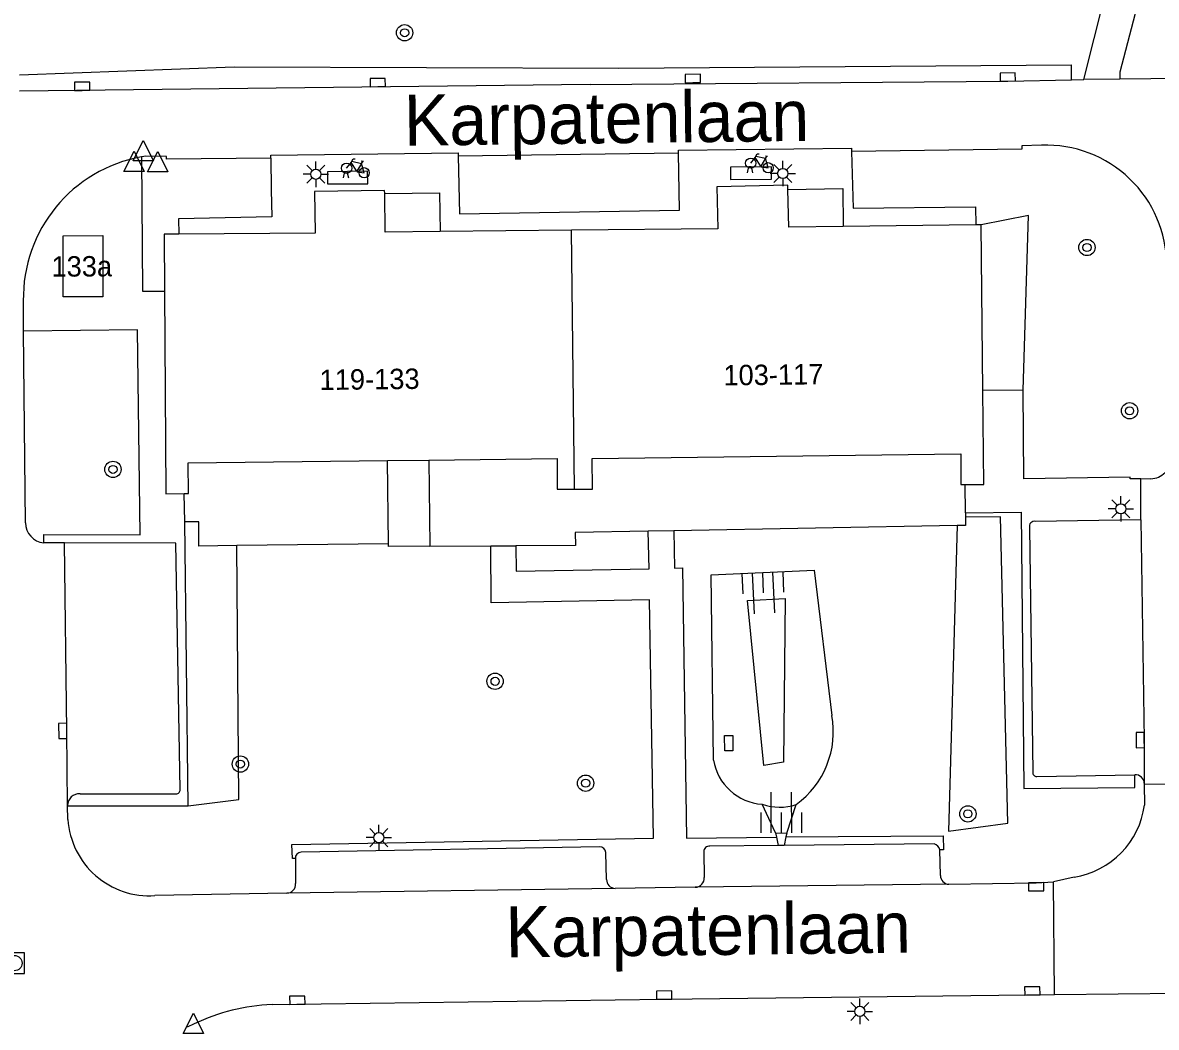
# Model space of a CAD drawing. Extents: x 132994 to 136000, y 393499 to 395512.
# Drawn here: x 133882.7 to 133938.3, y 394606.9 to 394656.2 of the extents above; entities that cross this region are included whole.
import ezdxf

# ---------------------------------------------------------------- set-up
doc = ezdxf.new("R2010")
doc.units = 0
for name, color, linetype in [('gg-afsc-erfafscheiding', 7, 'Continuous'), ('gg-anno-huisnummerreeks BGT', 7, 'Continuous'), ('gg-anno-openbare ruimte label', 7, 'Continuous'), ('gg-bbg-bijgebouw', 7, 'Continuous'), ('gg-bbg-hoofdgebouw', 7, 'Continuous'), ('gg-bbg-luifel en loopbrug', 7, 'Continuous'), ('gg-bbg-tussenscheiding', 7, 'Continuous'), ('gg-knt-bovenkant onderkant talud', 7, 'Continuous'), ('gg-knt-verharding', 7, 'Continuous'), ('gg-knt-verharding nz', 7, 'Continuous'), ('gt-grn-groengrens', 7, 'Continuous'), ('gt-symb-boom', 7, 'Continuous'), ('gt-symb-fietsenrek', 7, 'Continuous'), ('gt-symb-kolk', 7, 'Continuous'), ('gt-symb-kolk center center', 7, 'Continuous'), ('gt-symb-lichtmast', 7, 'Continuous'), ('gt-symb-rioolschacht', 7, 'Continuous'), ('gt-symb-talud symbool', 7, 'Continuous'), ('gt-symb-waterafsluiter', 7, 'Continuous')]:
    doc.layers.add(name, color=color, linetype=linetype)

# ---------------------------------------------------------------- blocks, each defined once
blk = doc.blocks.new('gt0-KOLK')
at = {"layer": 'gt-symb-kolk'}
blk.add_lwpolyline([(0, 0), (0.375, 0), (0.375, 0.4), (-0.375, 0.4), (-0.375, 0), (0, 0)], dxfattribs=at)
blk = doc.blocks.new('gt0-BOOM')
at = {"layer": 'gt-symb-boom'}
for radius in [0.4, 0.2]:
    blk.add_circle((0, 0), radius, dxfattribs=at)
blk = doc.blocks.new('gt0-LMAST')
at = {"layer": 'gt-symb-lichtmast'}
for p, q in [((-0.005, 0.246), (-0.005, 0.621)), ((-0.182, 0.173), (-0.447, 0.438)), ((0.172, 0.173), (0.437, 0.438)), ((-0.255, -0.004), (-0.63, -0.004)), ((-0.182, -0.181), (-0.447, -0.446)), ((-0.005, -0.254), (-0.005, -0.629)), ((0.437, -0.446), (0.172, -0.181)), ((0.245, -0.004), (0.62, -0.004))]:
    blk.add_line(p, q, dxfattribs=at)
blk.add_circle((-0.005, -0.004), 0.25, dxfattribs=at)
blk = doc.blocks.new('gt0-KOLKCC')
at = {"layer": 'gt-symb-kolk center center'}
blk.add_lwpolyline([(-0.375, 0.2), (0.375, 0.2), (0.375, -0.2), (-0.375, -0.2)], close=True, dxfattribs=at)
blk = doc.blocks.new('gt0-TALUD_1')
at = {"layer": 'gt-symb-talud symbool'}
for p, q in [((-1, -1), (-1, 0)), ((-0.5, -2), (-0.5, 0)), ((0, -1), (0, 0)), ((0.5, -2), (0.5, 0)), ((1, -1), (1, 0))]:
    blk.add_line(p, q, dxfattribs=at)
blk = doc.blocks.new('gt0-FREK')
at = {"layer": 'gt-symb-fietsenrek'}
for p, q in [((0.259, 0.762), (0.294, 0.823)), ((0.54, 0.335), (0.259, 0.762)), ((0.294, 0.823), (0.767, 0.714)), ((0.767, 0.714), (0.54, 0.335)), ((0.757, 0.841), (0.866, 0.816)), ((0.767, 0.714), (0.84, 0.822)), ((0.895, 0.252), (0.767, 0.714))]:
    blk.add_line(p, q, dxfattribs=at)
for points in [[(0.036, 0.476), (0.228, 0.708), (0.259, 0.762)], [(0.294, 0.823), (0.36, 0.937), (0.452, 0.935)], [(-0.124, 0), (-0.047, 0.312), (0.053, 0.312), (0.12, 0)], [(0.54, 0.335), (0.555, 0.305), (0.895, 0.252)]]:
    blk.add_lwpolyline(points, dxfattribs=at)
for centre in [(0.036, 0.476), (0.895, 0.252)]:
    blk.add_circle(centre, 0.252, dxfattribs=at)
blk = doc.blocks.new('gt0-WAFSL')
at = {"layer": 'gt-symb-waterafsluiter'}
for p, q in [((-0.5, -0.333), (0, 0.667)), ((0, 0.667), (0.5, -0.333)), ((0.5, -0.333), (-0.5, -0.333))]:
    blk.add_line(p, q, dxfattribs=at)
blk = doc.blocks.new('gt0-RS')
at = {"layer": 'gt-symb-rioolschacht'}
blk.add_lwpolyline([(-0.5, -0.5), (0.5, -0.5), (0.5, 0.5), (-0.5, 0.5)], close=True, dxfattribs=at)
blk.add_circle((0, 0), 0.375, dxfattribs=at)

msp = doc.modelspace()

# ---------------------------------------------------------------- linework, layer by layer
at = {"layer": 'gg-afsc-erfafscheiding'}
for p, q in [((133928.9, 394632.136), (133928.888, 394633.522)), ((133928.9, 394632.136), (133928.902, 394631.927)), ((133928.5, 394631.51), (133914.598, 394631.256)), ((133914.598, 394631.256), (133913.345, 394631.233)), ((133900.597, 394630.606), (133893.156, 394630.526)), ((133902.632, 394630.494), (133905.612, 394630.512)), ((133905.612, 394630.512), (133906.851, 394630.52))]:
    msp.add_line(p, q, dxfattribs=at)
for points in [[(133928.902, 394631.927), (133928.905, 394631.517), (133928.5, 394631.51)], [(133893.156, 394630.526), (133891.301, 394630.506), (133891.287, 394631.695), (133890.599, 394631.687)], [(133913.345, 394631.233), (133909.755, 394631.167), (133909.767, 394630.538), (133906.851, 394630.52)]]:
    msp.add_lwpolyline(points, dxfattribs=at)
at = {"layer": 'gg-bbg-bijgebouw'}
for p, q in [((133900.597, 394630.606), (133900.549, 394634.693)), ((133902.583, 394634.717), (133902.632, 394630.494))]:
    msp.add_line(p, q, dxfattribs=at)
msp.add_lwpolyline([(133902.632, 394630.494), (133900.598, 394630.487), (133900.597, 394630.606)], dxfattribs=at)
at = {"layer": 'gg-bbg-hoofdgebouw'}
for p, q in [((133890.308, 394645.805), (133889.59, 394645.8)), ((133889.59, 394645.8), (133889.61, 394643.007)), ((133909.569, 394645.995), (133903.128, 394645.928)), ((133929.411, 394646.257), (133922.91, 394646.181)), ((133929.67, 394646.26), (133929.411, 394646.257)), ((133929.753, 394638.129), (133929.67, 394646.26)), ((133889.61, 394643.007), (133889.68, 394633.121)), ((133929.8, 394633.53), (133929.753, 394638.129)), ((133900.549, 394634.693), (133902.583, 394634.717)), ((133928.68, 394633.52), (133928.888, 394633.522)), ((133928.888, 394633.522), (133929.8, 394633.53)), ((133890.574, 394633.076), (133890.79, 394633.08)), ((133908.88, 394633.29), (133909.727, 394633.295)), ((133909.727, 394633.295), (133910.6, 394633.3))]:
    msp.add_line(p, q, dxfattribs=at)
for points in [[(133920.194, 394647.99), (133920.19, 394648.2), (133916.71, 394648.12), (133916.75, 394646.07), (133909.569, 394645.995)], [(133922.91, 394646.181), (133920.23, 394646.15), (133920.194, 394647.99)], [(133900.412, 394647.789), (133900.41, 394647.95), (133896.97, 394647.9), (133897, 394645.85), (133890.308, 394645.805)], [(133903.128, 394645.928), (133900.44, 394645.9), (133900.412, 394647.789)], [(133886.59, 394642.72), (133884.64, 394642.72), (133884.63, 394645.72), (133886.58, 394645.73), (133886.59, 394642.72)], [(133890.79, 394633.08), (133890.77, 394634.58), (133900.549, 394634.693)], [(133902.583, 394634.717), (133908.87, 394634.79), (133908.88, 394633.29)], [(133910.6, 394633.3), (133910.59, 394634.8), (133928.67, 394635.02), (133928.68, 394633.52)], [(133889.68, 394633.121), (133889.68, 394633.06), (133890.574, 394633.076)]]:
    msp.add_lwpolyline(points, dxfattribs=at)
at = {"layer": 'gg-bbg-luifel en loopbrug'}
for points in [[(133920.194, 394647.99), (133922.889, 394648.042), (133922.91, 394646.181)], [(133900.412, 394647.789), (133903.108, 394647.828), (133903.128, 394645.928)]]:
    msp.add_lwpolyline(points, dxfattribs=at)
at = {"layer": 'gg-bbg-tussenscheiding'}
msp.add_line((133909.727, 394633.295), (133909.569, 394645.995), dxfattribs=at)
at = {"layer": 'gg-knt-bovenkant onderkant talud'}
for p, q in [((133919.588, 394616.443), (133918.931, 394617.845)), ((133920.134, 394616.426), (133920.601, 394617.829))]:
    msp.add_line(p, q, dxfattribs=at)
for points in [[(133916.542, 394620.007), (133916.429, 394629.086), (133921.481, 394629.317), (133922.351, 394622.191)], [(133919.982, 394619.903), (133919.011, 394619.737), (133918.205, 394627.831), (133920.06, 394627.937), (133919.982, 394619.903)]]:
    msp.add_lwpolyline(points, dxfattribs=at)
for centre, radius, start, end in [((133918.001, 394621.404), 4.421, 306.029, 10.2504), ((133919.087, 394620.419), 2.578, 189.1875, 266.5235), ((133919.789, 394620.239), 2.543, 250.2834, 288.6188)]:
    msp.add_arc(centre, radius, start, end, dxfattribs=at)
at = {"layer": 'gg-knt-verharding'}
for p, q in [((133934.704, 394653.385), (133936.164, 394659.176)), ((133910.498, 394653.146), (133882.497, 394652.812)), ((133934.112, 394653.373), (133934.704, 394653.385)), ((133936.481, 394653.399), (133934.702, 394653.379)), ((133934.702, 394653.379), (133934.704, 394653.385)), ((133941.316, 394653.452), (133936.481, 394653.399)), ((133914.832, 394649.767), (133904.021, 394649.626)), ((133882.695, 394641.049), (133882.684, 394642.526)), ((133882.794, 394631.643), (133882.695, 394641.049)), ((133931.729, 394638.149), (133929.753, 394638.129)), ((133937.506, 394633.807), (133937.994, 394633.809)), ((133890.599, 394631.687), (133890.574, 394633.076)), ((133890.774, 394617.756), (133890.599, 394631.687)), ((133932.051, 394631.397), (133932.202, 394619.413)), ((133937.505, 394631.796), (133932.342, 394631.714)), ((133884.709, 394630.66), (133883.682, 394630.662)), ((133932.403, 394619.197), (133937.214, 394619.283)), ((133937.675, 394618.822), (133943.037, 394618.89)), ((133937.675, 394618.867), (133937.675, 394618.822)), ((133937.675, 394618.822), (133937.688, 394617.803)), ((133885.467, 394618.355), (133890.182, 394618.353)), ((133884.856, 394617.757), (133884.856, 394617.782)), ((133884.856, 394617.757), (133890.774, 394617.756)), ((133884.873, 394617.092), (133884.856, 394617.757)), ((133919.588, 394616.443), (133919.629, 394616.23)), ((133919.588, 394616.443), (133920.134, 394616.426)), ((133920.134, 394616.426), (133920.097, 394616.235)), ((133910.95, 394615.751), (133896.306, 394615.488)), ((133919.708, 394615.817), (133916.368, 394615.783)), ((133919.629, 394616.23), (133919.708, 394615.817)), ((133920.016, 394615.82), (133919.708, 394615.817)), ((133920.097, 394616.235), (133920.016, 394615.82)), ((133927.363, 394615.896), (133920.016, 394615.82)), ((133896.028, 394615.179), (133896.04, 394613.951)), ((133911.297, 394614.157), (133911.264, 394615.467)), ((133916.064, 394615.507), (133916.085, 394614.247)), ((133927.672, 394614.348), (133927.65, 394615.6)), ((133934.237, 394614.269), (133933.228, 394614.039)), ((133933.267, 394608.502), (133933.228, 394614.039)), ((133895.617, 394613.475), (133889.141, 394613.363)), ((133915.648, 394613.768), (133911.715, 394613.715)), ((133933.267, 394608.502), (133947.183, 394608.664)), ((133891.063, 394607.071), (133890.725, 394606.9))]:
    msp.add_line(p, q, dxfattribs=at)
for points in [[(133937.779, 394658.768), (133936.478, 394653.738), (133936.481, 394653.399)], [(133910.498, 394653.146), (133930.982, 394653.305), (133934.112, 394653.373)], [(133894.831, 394649.529), (133889.701, 394649.476), (133889.703, 394649.615), (133888.699, 394649.63), (133888.589, 394649.613), (133888.479, 394649.594)], [(133904.021, 394649.626), (133904.077, 394646.798), (133914.87, 394646.978), (133914.832, 394649.767)], [(133932.64, 394650.164), (133931.662, 394650.13), (133931.664, 394649.973), (133923.314, 394649.863)], [(133923.314, 394649.863), (133923.39, 394647.071), (133929.4, 394647.14), (133929.411, 394646.257)], [(133888.479, 394649.594), (133888.523, 394643), (133889.61, 394643.007)], [(133894.831, 394649.529), (133894.846, 394647.979), (133894.868, 394646.645), (133890.303, 394646.554), (133890.308, 394645.805)], [(133883.682, 394630.662), (133883.683, 394631.072), (133888.41, 394631.049), (133888.291, 394641.115), (133882.695, 394641.049)], [(133937.506, 394633.807), (133936.983, 394633.805), (133936.983, 394633.876), (133931.768, 394633.795), (133931.729, 394638.149)], [(133928.9, 394632.136), (133931.631, 394632.161), (133931.772, 394618.61), (133937.218, 394618.66), (133937.214, 394619.283)], [(133906.851, 394630.52), (133906.861, 394629.277), (133913.378, 394629.393), (133913.345, 394631.233)], [(133914.598, 394631.256), (133914.629, 394629.426), (133915.018, 394629.43), (133915.225, 394616.177), (133919.629, 394616.23)], [(133890.376, 394618.556), (133890.172, 394630.649), (133884.709, 394630.66)], [(133896.028, 394615.179), (133895.882, 394615.177), (133895.864, 394615.872), (133913.6, 394616.176), (133913.4, 394627.869), (133905.629, 394627.721), (133905.612, 394630.512)], [(133920.097, 394616.235), (133927.81, 394616.293), (133927.823, 394615.603), (133927.65, 394615.6)], [(133928.082, 394613.915), (133932.373, 394613.994), (133933.228, 394614.039)], [(133894.884, 394608.012), (133914.124, 394608.279), (133933.267, 394608.502)]]:
    msp.add_lwpolyline(points, dxfattribs=at)
for centre, radius, start, end in [((133932.858, 394644.249), 5.919, 0.2225, 92.1111), ((133889.733, 394642.656), 7.051, 100.2488, 181.055), ((133937.982, 394634.797), 0.989, 270.7122, 1.3061), ((133883.775, 394631.639), 0.981, 179.7612, 264.5415), ((133932.285, 394631.474), 0.247, 76.7311, 198.1663), ((133932.405, 394619.4), 0.203, 176.4342, 269.4456), ((133937.238, 394618.846), 0.438, 2.7425, 93.1322), ((133890.191, 394618.539), 0.186, 267.2628, 5.3346), ((133885.435, 394617.776), 0.58, 86.8821, 179.4414), ((133933.587, 394618.356), 4.138, 279.0364, 352.3251), ((133888.86, 394617.348), 3.995, 183.6727, 274.0391), ((133910.958, 394615.445), 0.306, 4.1689, 91.5751), ((133916.334, 394615.515), 0.27, 82.6974, 181.7749), ((133927.279, 394615.528), 0.378, 11.039, 77.1922), ((133896.314, 394615.201), 0.287, 91.6468, 184.3993), ((133911.725, 394614.144), 0.429, 178.1996, 268.6034), ((133915.635, 394614.219), 0.451, 271.6909, 3.5596), ((133928.106, 394614.349), 0.434, 180.0928, 266.7815), ((133895.594, 394613.921), 0.447, 272.9271, 3.8207), ((133895.259, 394598.262), 9.757, 92.2007, 115.4693)]:
    msp.add_arc(centre, radius, start, end, dxfattribs=at)
at = {"layer": 'gg-knt-verharding nz'}
for p, q in [((133937.505, 394631.796), (133937.506, 394633.807)), ((133911.715, 394613.715), (133895.617, 394613.475)), ((133928.082, 394613.915), (133915.648, 394613.768))]:
    msp.add_line(p, q, dxfattribs=at)
for points in [[(133894.831, 394649.529), (133894.829, 394649.683), (133904.019, 394649.79), (133904.021, 394649.626)], [(133914.832, 394649.767), (133914.83, 394649.916), (133923.312, 394650.015), (133923.314, 394649.863)], [(133917.375, 394649.079), (133917.369, 394648.484), (133919.39, 394648.503), (133919.384, 394649.108), (133917.375, 394649.079)], [(133897.609, 394648.863), (133897.611, 394648.27), (133899.588, 394648.274), (133899.576, 394648.887), (133897.609, 394648.863)], [(133937.505, 394631.796), (133937.676, 394620.992), (133937.675, 394618.867)], [(133884.856, 394617.782), (133884.818, 394621.437), (133884.709, 394630.66)]]:
    msp.add_lwpolyline(points, dxfattribs=at)
at = {"layer": 'gt-grn-groengrens'}
msp.add_line((133934.112, 394653.373), (133934.106, 394654.11), dxfattribs=at)
for points in [[(133882.488, 394653.615), (133893.02, 394654.001), (133911.896, 394653.948), (133934.106, 394654.11)], [(133931.729, 394638.149), (133931.999, 394646.714), (133929.67, 394646.26)], [(133928.5, 394631.51), (133928.078, 394616.521), (133930.979, 394616.905), (133930.624, 394631.942), (133928.902, 394631.927)], [(133890.774, 394617.756), (133893.257, 394618.067), (133893.156, 394630.526)]]:
    msp.add_lwpolyline(points, dxfattribs=at)

# ---------------------------------------------------------------- block references
at = {"layer": 'gt-symb-boom'}
for p in [(133901.388, 394655.678), (133934.863, 394645.147), (133936.954, 394637.137), (133887.082, 394634.262), (133905.827, 394623.871), (133893.332, 394619.81), (133910.27, 394618.874), (133929.021, 394617.369)]:
    msp.add_blockref('gt0-BOOM', p, dxfattribs=at)
at = {"layer": 'gt-symb-fietsenrek'}
for p in [(133918.33, 394648.806), (133898.508, 394648.56)]:
    msp.add_blockref('gt0-FREK', p, dxfattribs=at)
at = {"layer": 'gt-symb-kolk'}
for p, rotation in [((133915.532, 394653.235), 0.7448031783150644), ((133930.982, 394653.305), 1.2603038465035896), ((133885.575, 394652.854), 0.7448031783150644), ((133900.073, 394653.038), 0.7448031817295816), ((133884.818, 394621.437), 90.67783393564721), ((133937.676, 394620.992), 90.66169648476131), ((133932.371, 394613.994), -178.9428235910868), ((133914.124, 394608.279), 0.6697652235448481), ((133932.186, 394608.489), 0.6697652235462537), ((133896.128, 394608.029), 0.7989737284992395)]:
    msp.add_blockref('gt0-KOLK', p, dxfattribs=dict(at, rotation=rotation))
at = {"layer": 'gt-symb-kolk center center', "rotation": 90.64555892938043}
msp.add_blockref('gt0-KOLKCC', (133917.29, 394620.834), dxfattribs=at)
at = {"layer": 'gt-symb-lichtmast'}
for p in [(133897.037, 394648.742), (133919.945, 394648.781), (133936.529, 394632.334), (133900.127, 394616.206), (133923.729, 394607.687)]:
    msp.add_blockref('gt0-LMAST', p, dxfattribs=at)
at = {"layer": 'gt-symb-rioolschacht'}
msp.add_blockref('gt0-RS', (133882.247, 394610.047), dxfattribs=at)
at = {"layer": 'gt-symb-talud symbool'}
for p, xscale, yscale, rotation in [((133918.955, 394629.202), 1.0000129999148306, 1.0000129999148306, 2.5791474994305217), ((133919.861, 394616.434), 1.0000004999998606, 1.0000004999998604, -179.94270424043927)]:
    msp.add_blockref('gt0-TALUD_1', p, dxfattribs=dict(at, xscale=xscale, yscale=yscale, rotation=rotation))
at = {"layer": 'gt-symb-waterafsluiter'}
for p in [(133888.567, 394649.724), (133888.119, 394649.208), (133889.279, 394649.183), (133891.026, 394606.923)]:
    msp.add_blockref('gt0-WAFSL', p, dxfattribs=at)

# ---------------------------------------------------------------- texts
at = {"layer": 'gg-anno-huisnummerreeks BGT'}
for s, rotation, p in [('133a', 0.3, (133884.066, 394643.715)), ('119-133', 0.7, (133897.222, 394638.154)), ('103-117', 0.7, (133917.032, 394638.379))]:
    msp.add_text(s, height=1, rotation=rotation, dxfattribs=at).set_placement(p)
at = {"layer": 'gg-anno-openbare ruimte label'}
for p in [(133901.365, 394650.137), (133906.348, 394610.323)]:
    msp.add_text('Karpatenlaan', height=2.5, rotation=0.7, dxfattribs=at).set_placement(p)

doc.saveas('drawing.dxf')
